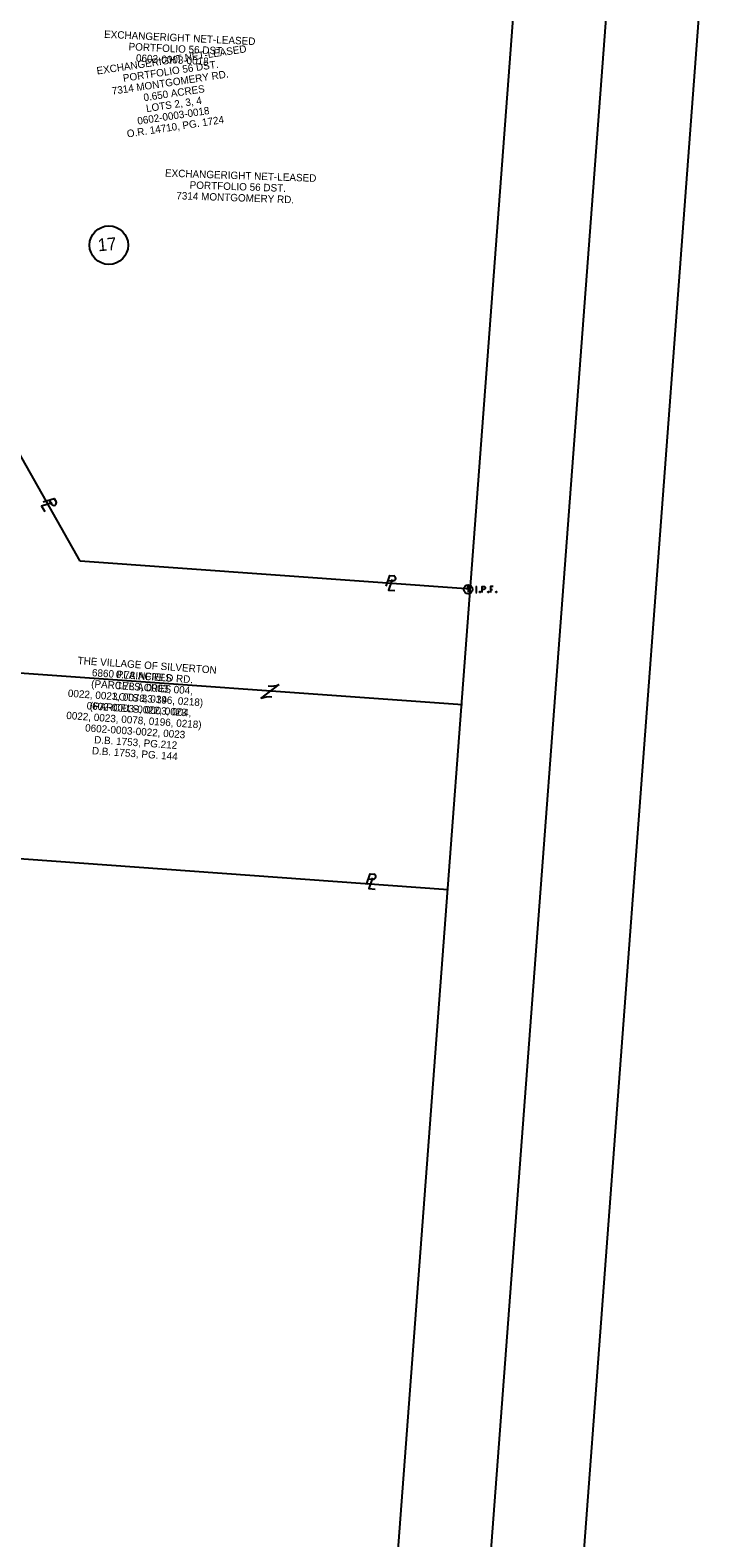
# Model space of a CAD drawing. Extents: x 204354 to 231038, y 361459 to 365260.
# Drawn here: x 220781.9 to 220965.9, y 361736.1 to 362142.9 of the extents above; entities that cross this region are included whole.
import ezdxf

# ---------------------------------------------------------------- set-up
doc = ezdxf.new("R2010")
doc.units = 0
for name, color, linetype in [('CM_Corridor_Point_Control', 7, 'Continuous'), ('CM_Corridor_Range_Conceptual', 7, 'Continuous'), ('DT_P_Contour_Minor', 7, 'Continuous'), ('DT_P_Contour_Text', 7, 'Continuous'), ('DT_X_Contour_Minor', 7, 'Continuous'), ('MD_P_Surface_Finished_Grade', 7, 'Continuous'), ('MD_P_SW_BOT', 7, 'Continuous'), ('PV_P_Walk', 7, 'Continuous')]:
    doc.layers.add(name, color=color, linetype=linetype)

msp = doc.modelspace()

# ---------------------------------------------------------------- linework, layer by layer
at = {"layer": 'CM_Corridor_Range_Conceptual'}
msp.add_line((220891.46, 361535.2), (220942.8, 362219.1), dxfattribs=at)
at = {"layer": 'DT_P_Contour_Text'}
msp.add_circle((220803.12, 362084.89), 5.2, dxfattribs=at)
at = {"layer": 'MD_P_Surface_Finished_Grade'}
msp.add_line((220900.09, 361992.13), (220900.09, 361991.25), dxfattribs=at)
for points in [[(220902.12, 361992.82), (220902.47, 361992.82)], [(220902.12, 361991.22), (220902.47, 361991.22)], [(220902.3, 361991.22), (220902.3, 361992.82)], [(220903.26, 361991.43), (220903.31, 361991.43), (220903.34, 361991.41), (220903.38, 361991.35), (220903.38, 361991.29), (220903.34, 361991.24), (220903.31, 361991.22), (220903.26, 361991.22), (220903.22, 361991.24), (220903.19, 361991.29), (220903.19, 361991.35), (220903.22, 361991.41), (220903.26, 361991.43)], [(220903.86, 361991.22), (220903.86, 361992.82), (220904.39, 361992.82), (220904.45, 361992.8), (220904.52, 361992.78), (220904.56, 361992.75), (220904.59, 361992.73), (220904.63, 361992.66), (220904.67, 361992.6), (220904.69, 361992.5), (220904.69, 361992.35), (220904.68, 361992.3), (220904.66, 361992.22), (220904.61, 361992.14), (220904.57, 361992.1), (220904.53, 361992.07), (220904.48, 361992.05), (220904.39, 361992.03), (220903.86, 361992.03)], [(220905.5, 361991.43), (220905.56, 361991.43), (220905.59, 361991.41), (220905.63, 361991.35), (220905.63, 361991.29), (220905.59, 361991.24), (220905.56, 361991.22), (220905.5, 361991.22), (220905.47, 361991.24), (220905.44, 361991.29), (220905.44, 361991.35), (220905.47, 361991.41), (220905.5, 361991.43)], [(220906.87, 361992.82), (220906.11, 361992.82), (220906.11, 361991.22)], [(220906.11, 361992.03), (220906.65, 361992.03)], [(220907.65, 361991.43), (220907.71, 361991.43), (220907.74, 361991.41), (220907.78, 361991.35), (220907.78, 361991.29), (220907.74, 361991.24), (220907.71, 361991.22), (220907.65, 361991.22), (220907.62, 361991.24), (220907.59, 361991.29), (220907.59, 361991.35), (220907.62, 361991.41), (220907.65, 361991.43)]]:
    msp.add_lwpolyline(points, dxfattribs=at)
for centre, radius in [((220900.09, 361992.02), 1.2), ((220900.09, 361992.67), 0.16)]:
    msp.add_circle(centre, radius, dxfattribs=at)
at = {"layer": 'MD_P_SW_BOT'}
for p, q in [((220795.34, 361999.62), (220778.84, 362028.98)), ((220786.88, 362015.08), (220786.88, 362015.08)), ((220786.98, 362016.1), (220787.68, 362015)), ((220900.82, 361992.06), (220795.34, 361999.62)), ((220878.51, 361994.45), (220879.8, 361994.35)), ((220879.26, 361993.77), (220879.26, 361993.77)), ((220898.55, 361960.84), (220579.12, 361983.8)), ((220844.15, 361962.54), (220849.09, 361966.37)), ((220846.62, 361964.46), (220846.62, 361964.46)), ((220894.66, 361910.99), (220735.27, 361922.44)), ((220873.17, 361913.94), (220874.46, 361913.84)), ((220873.92, 361913.25), (220873.92, 361913.25))]:
    msp.add_line(p, q, dxfattribs=at)
for points in [[(220787.84, 362015.37), (220784.92, 362014.46), (220785.85, 362012.99)], [(220785.41, 362015.6), (220788.34, 362016.52), (220788.89, 362015.65)], [(220877.97, 361992.89), (220878.97, 361995.79), (220880, 361995.71)], [(220879.6, 361994.71), (220878.59, 361991.82), (220880.33, 361991.69)], [(220872.63, 361912.38), (220873.63, 361915.28), (220874.66, 361915.2)], [(220874.26, 361914.19), (220873.25, 361911.3), (220874.99, 361911.17)]]:
    msp.add_lwpolyline(points, dxfattribs=at)
for centre, radius, start, end in [((220788.26, 362015.37), 0.69, 212.6944, 23.5516), ((220879.85, 361995.04), 0.69, 266.2039, 77.061), ((220846.94, 361971.25), 5.34, 261.2021, 293.8446), ((220846.31, 361957.66), 5.34, 81.2021, 113.8446), ((220874.5, 361914.53), 0.69, 266.2039, 77.061)]:
    msp.add_arc(centre, radius, start, end, dxfattribs=at)
at = {"layer": 'PV_P_Walk'}
for p, q in [((220919.73, 361577.82), (220965.86, 362192.34)), ((220868.4, 361561.94), (220915.12, 362184.41))]:
    msp.add_line(p, q, dxfattribs=at)

# ---------------------------------------------------------------- texts
at = {"layer": 'CM_Corridor_Point_Control'}
for s, rotation, p in [('EXCHANGERIGHT NET-LEASED', 358, (220818.25, 362103.38)), ('7314 MONTGOMERY RD.', 358, (220821.3, 362097.27)), ('PORTFOLIO 56 DST.', 358, (220824.9, 362100.15)), ('THE VILLAGE OF SILVERTON', 356, (220794.64, 361971.88)), ('6860 PLAINFIELD RD.', 356, (220798.5, 361968.6))]:
    msp.add_text(s, height=2, rotation=rotation, dxfattribs=at).set_placement(p)
at = {"layer": 'DT_P_Contour_Minor'}
for s, rotation, p in [('EXCHANGERIGHT NET-LEASED', 8.4719, (220799.96, 362130.91)), ('7314 MONTGOMERY RD.', 8.4719, (220804.07, 362125.46)), ('PORTFOLIO 56 DST.', 8.4719, (220807.08, 362128.94)), (' 0.650 ACRES', 8.4719, (220811.89, 362123.59)), ('LOTS 2, 3, 4', 8.4719, (220813.32, 362120.77)), ('O.R. 14710, PG. 1724', 8.4719, (220808.13, 362113.93)), (' 0602-0003-0018', 8.4719, (220810.23, 362117.28)), ('THE VILLAGE OF SILVERTON', 356, (220794.64, 361971.88)), ('6860 PLAINFIELD RD.', 356, (220798.5, 361968.6)), (' 0.78 ACRES ', 356, (220804.01, 361965.21)), ('(PARCELS, 0003, 004,', 356, (220797.88, 361959.63)), ('LOTS 33-34', 356, (220804.2, 361962.19)), ('0022, 0023, 0078, 0196, 0218)', 356, (220791.58, 361957.06)), (' 0602-0003-0022, 0023', 356, (220795.92, 361953.75)), ('D.B. 1753, PG.212', 356, (220799.1, 361950.52)), ('D.B. 1753, PG. 144', 356, (220798.49, 361947.55))]:
    msp.add_text(s, height=2, rotation=rotation, dxfattribs=at).set_placement(p)
at = {"layer": 'DT_P_Contour_Text'}
msp.add_text('17', height=3.4, rotation=5.0398, dxfattribs=at).set_placement((220800.27, 362083.21))
at = {"layer": 'DT_X_Contour_Minor'}
for s, rotation, p in [('EXCHANGERIGHT NET-LEASED', 357.2486, (220801.8, 362140.82)), ('PORTFOLIO 56 DST.', 357.2486, (220808.41, 362137.5)), (' 0602-0003-0018', 357.2486, (220809.66, 362134.44)), ('THE VILLAGE OF SILVERTON', 356, (220794.64, 361971.88)), (' 0.78 ACRES ', 356, (220804.22, 361968.2)), ('0022, 0023, 0078, 0196, 0218)', 356, (220792, 361963.04)), ('(PARCELS, 0003, 004,', 356, (220798.3, 361965.61)), (' 0602-0003-0022, 0023', 356, (220796.34, 361959.73))]:
    msp.add_text(s, height=2, rotation=rotation, dxfattribs=at).set_placement(p)

doc.saveas('drawing.dxf')
